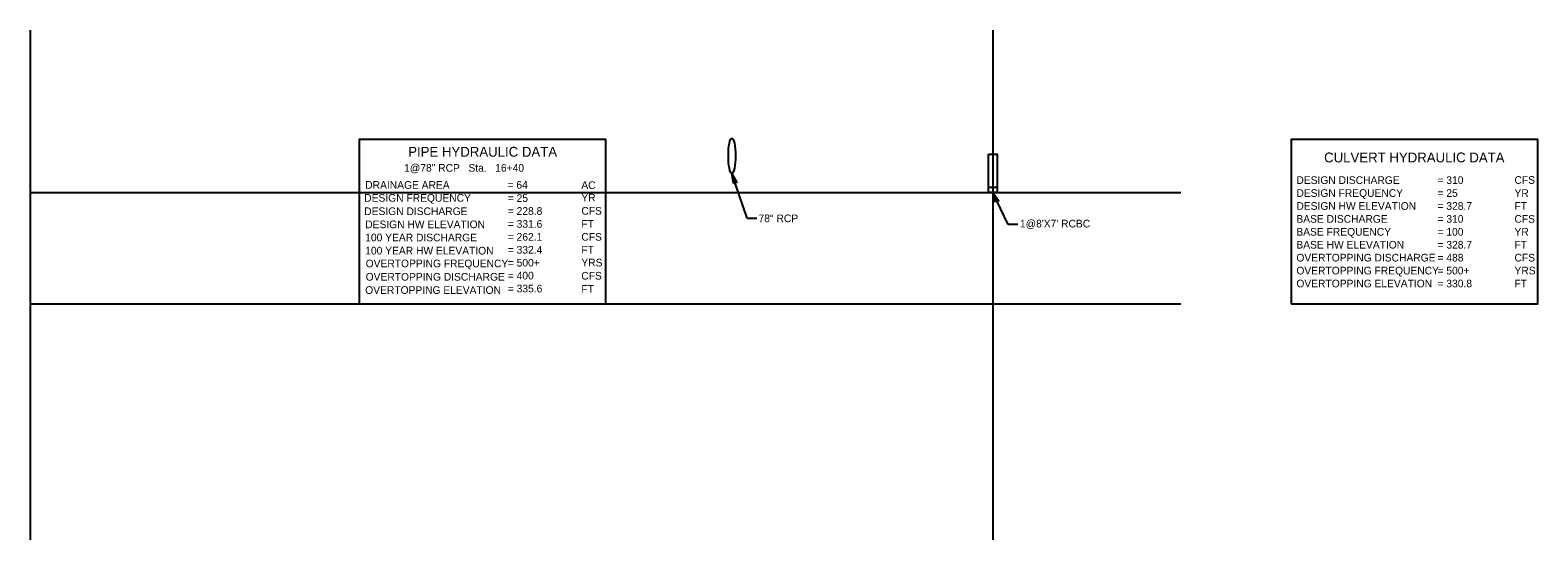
# Model space of a CAD drawing. Extents: x 2044939 to 2046718, y 752715 to 754848.
# Drawn here: x 2044939 to 2046314, y 754382 to 754848 of the extents above; entities that cross this region are included whole.
import ezdxf

# ---------------------------------------------------------------- set-up
doc = ezdxf.new("R2010")
doc.units = 0
for name, color, linetype in [('Prop Drainage Structure Box Reinforced Concrete', 7, 'Continuous'), ('Prop Drainage Structure Box Reinforced Concrete Label', 7, 'Continuous'), ('Prop Grid Mask', 7, 'Continuous'), ('Prop PFL Cross Pipe Text CELL', 7, 'Continuous'), ('Prop PFL Culvert Hydraulic Data Label CELL', 7, 'Continuous'), ('Prop PFL Pipe Hydraulic Data CELL', 7, 'Continuous'), ('Prop Terminator CELL', 7, 'Continuous'), ('Scratch_Level_0', 7, 'Continuous')]:
    doc.layers.add(name, color=color, linetype=linetype)

msp = doc.modelspace()

# ---------------------------------------------------------------- linework, layer by layer
at = {"layer": 'Prop Drainage Structure Box Reinforced Concrete'}
for p, q in [((2045813.4, 754704.3), (2045821.4, 754704.3)), ((2045813.4, 754699.3), (2045821.4, 754699.3))]:
    msp.add_line(p, q, dxfattribs=at)
msp.add_lwpolyline([(2045813.4, 754734.3), (2045821.4, 754734.3), (2045821.4, 754699.3), (2045813.4, 754699.3)], close=True, dxfattribs=at)
at = {"layer": 'Prop Drainage Structure Box Reinforced Concrete Label'}
for p, q in [((2045831.3, 754670.1), (2045817.4, 754699.3)), ((2045840.3, 754670.1), (2045831.3, 754670.1))]:
    msp.add_line(p, q, dxfattribs=at)
at = {"layer": 'Prop Grid Mask'}
for points in [[(2045239.4, 754597.7), (2045464.4, 754597.7), (2045464.4, 754747.7), (2045239.4, 754747.7)], [(2046089.4, 754597.7), (2046314.4, 754597.7), (2046314.4, 754747.7), (2046089.4, 754747.7)]]:
    msp.add_lwpolyline(points, close=True, dxfattribs=at)
at = {"layer": 'Prop PFL Cross Pipe Text CELL'}
for q in [(2045579.4, 754716.7), (2045602.2, 754675.9)]:
    msp.add_line((2045593.2, 754675.9), q, dxfattribs=at)
msp.add_ellipse((2045579.4, 754733), major_axis=(0, 16.2), ratio=0.2, dxfattribs=at)
at = {"layer": 'Prop Terminator CELL'}
for points in [[(2045580.8, 754707.7), (2045579.4, 754716.7), (2045583.8, 754708.6), (2045581.9, 754709.2)], [(2045819.9, 754690.5), (2045817.4, 754699.3), (2045822.7, 754691.8), (2045820.8, 754692.2)]]:
    msp.add_lwpolyline(points, close=True, dxfattribs=at)
at = {"layer": 'Scratch_Level_0'}
for p, q in [((2044939.4, 754847.7), (2044939.4, 754382.2)), ((2045817.4, 754847.7), (2045817.4, 754382.2)), ((2044939.4, 754699.3), (2045988.9, 754699.3)), ((2044939.4, 754597.7), (2045988.9, 754597.7))]:
    msp.add_line(p, q, dxfattribs=at)

# ---------------------------------------------------------------- texts
at = {"layer": 'Prop Drainage Structure Box Reinforced Concrete Label'}
msp.add_text("1@8'X7' RCBC", height=7, dxfattribs=at).set_placement((2045842.1, 754667.5))
at = {"layer": 'Prop PFL Cross Pipe Text CELL'}
msp.add_text('78" RCP', height=7, dxfattribs=at).set_placement((2045603.7, 754672.3))
at = {"layer": 'Prop PFL Culvert Hydraulic Data Label CELL'}
for s, height, p in [('CULVERT HYDRAULIC DATA', 9, (2046119.5, 754726.9)), ('DESIGN DISCHARGE', 7, (2046094.2, 754707.2)), ('= 310     ', 7, (2046222.9, 754707.2)), ('CFS', 7, (2046293.1, 754707.3)), ('DESIGN FREQUENCY', 7, (2046094.2, 754695.4)), ('= 25 ', 7, (2046222.9, 754695.4)), ('YR', 7, (2046293.1, 754695.4)), ('DESIGN HW ELEVATION', 7, (2046094.2, 754683.6)), ('= 328.7   ', 7, (2046222.9, 754683.6)), ('FT', 7, (2046293.1, 754683.6)), ('BASE DISCHARGE', 7, (2046094.2, 754671.8)), ('= 310     ', 7, (2046222.9, 754671.8)), ('CFS', 7, (2046293.1, 754671.8)), ('BASE FREQUENCY', 7, (2046094.2, 754660)), ('BASE HW ELEVATION', 7, (2046094.2, 754648.2)), ('= 100', 7, (2046222.9, 754660)), ('= 328.7   ', 7, (2046222.9, 754648.2)), ('YR', 7, (2046293.1, 754660)), ('FT', 7, (2046293.1, 754648.2)), ('OVERTOPPING DISCHARGE', 7, (2046094.2, 754636.4)), ('= 488     ', 7, (2046222.9, 754636.4)), ('CFS', 7, (2046293.1, 754636.4)), ('OVERTOPPING FREQUENCY', 7, (2046094.2, 754624.6)), ('= 500+', 7, (2046222.9, 754624.6)), ('YRS', 7, (2046293.1, 754624.6)), ('OVERTOPPING ELEVATION', 7, (2046094.2, 754612.8)), ('= 330.8   ', 7, (2046222.9, 754612.8)), ('FT', 7, (2046293.1, 754612.8))]:
    msp.add_text(s, height=height, dxfattribs=at).set_placement(p)
at = {"layer": 'Prop PFL Pipe Hydraulic Data CELL'}
for s, height, p in [('PIPE HYDRAULIC DATA', 9, (2045284.2, 754732.1)), (' 1@78" RCP   Sta.   16+40   ', 7, (2045277.9, 754718.4)), ('DESIGN FREQUENCY', 7, (2045244.1, 754691)), ('DRAINAGE AREA', 7, (2045245, 754702.8)), ('= 64     ', 7, (2045374.8, 754702.9)), ('= 25 ', 7, (2045375, 754690.8)), ('AC', 7, (2045442.1, 754702.6)), ('YR', 7, (2045442.1, 754691.2)), ('DESIGN DISCHARGE', 7, (2045244.1, 754678.8)), ('= 228.8   ', 7, (2045375, 754679)), ('CFS', 7, (2045442.1, 754679.2)), ('DESIGN HW ELEVATION', 7, (2045245, 754666.8)), ('= 331.6   ', 7, (2045375, 754667.2)), ('FT', 7, (2045442.1, 754667.2)), ('100 YEAR DISCHARGE', 7, (2045245, 754654.8)), ('= 262.1   ', 7, (2045375, 754655.4)), ('CFS', 7, (2045442.1, 754655.4)), ('100 YEAR HW ELEVATION', 7, (2045245, 754642.8)), ('= 332.4   ', 7, (2045375, 754643.6)), ('FT', 7, (2045442.1, 754643.6)), ('OVERTOPPING FREQUENCY', 7, (2045245.4, 754631.1)), ('= 500+', 7, (2045375, 754631.8)), ('YRS', 7, (2045442.1, 754631.9)), ('OVERTOPPING ELEVATION', 7, (2045245, 754606.8)), ('OVERTOPPING DISCHARGE', 7, (2045245.4, 754618.9)), ('= 400     ', 7, (2045375, 754620)), ('= 335.6   ', 7, (2045375, 754608.2)), ('CFS', 7, (2045442.1, 754619.9)), ('FT', 7, (2045442.1, 754607.8))]:
    msp.add_text(s, height=height, dxfattribs=at).set_placement(p)

doc.saveas('drawing.dxf')
